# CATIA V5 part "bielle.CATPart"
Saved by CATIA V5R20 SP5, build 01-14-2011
Part number: bielle
Bounding box of the stored display mesh (mm): x 0 to 20, y -95 to 85, z -10 to 20
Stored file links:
  M:\EU_thinkMotion\IAO_2010\iao\IAO_MMS_Groupe2\IAO_MMS_Groupe2\rwatrin\rwatrin\bielle.CATPart
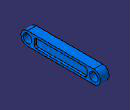
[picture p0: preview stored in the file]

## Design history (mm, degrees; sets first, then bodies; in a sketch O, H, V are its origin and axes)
Parameters
  `Longueur bielle` = 225.81 mm
Set1
  Plane1: type Offset, RefPlane yz-plane, Offset 10
Body1 (main body)
  Sketch1 on yz-plane, origin (0, 0, 0), H (0, 1, 0), V (0, 0, 1)
    line L1 (-80, 20) -> (70, 20)
    arc A1 centre (70, 5) radius 15 from (70, 20) to (70, -10) cw
    point P3 (70, 5)
    line L2 (70, -10) -> (-80, -10)
    arc A2 centre (-80, 5) radius 15 from (-80, -10) to (-80, 20) cw
    point P6 (-80, 5)
    circle A3 centre (70, 5) radius 10
    point P7 (70, 5)
    circle A4 centre (-80, 5) radius 10
    radius A3 = 10
    radius A4 = 10
    distance P6 P7 = 150
    distance L1 L2 = 30
    horizontal: L1 H
    tangency: A1 L1, L2 A1, A2 L1, A2 L2
    coincidence: P3 P7
  Pad1: profile Sketch1, direction (1, 0, 0), length 20
  Sketch2 on end face of Pad1, origin (20, 0, 0), H (0, 1, 0), V (0, 0, 1)
    line L1 (-60, 15) -> (50, 15)
    line L2 (55, 10) -> (55, 0)
    line L3 (50, -5) -> (-60, -5)
    line L4 (-65, 0) -> (-65, 10)
    reference projected line E1 (70, 20) -> (-80, 20) from edge [face of Pad1 from Sketch1.L1 | end face of Pad1]
    reference projected line E2 (-80, -10) -> (70, -10) from edge [face of Pad1 from Sketch1.L2 | end face of Pad1]
    reference projected circle E3 centre (70, 5) radius 10 from edge [end face of Pad1 | face of Pad1 from Sketch1.A3]
    reference projected circle E4 centre (-80, 5) radius 10 from edge [end face of Pad1 | face of Pad1 from Sketch1.A4]
    arc A1 centre (-60, 10) radius 5 from (-60, 15) to (-65, 10) ccw
    arc A2 centre (-60, 0) radius 5 from (-60, -5) to (-65, 0) cw
    arc A3 centre (50, 0) radius 5 from (55, 0) to (50, -5) cw
    arc A4 centre (50, 10) radius 5 from (50, 15) to (55, 10) cw
    distance L1 E1 = 5
    distance L3 E2 = 5
    distance L2 E3 = 5
    distance L4 E4 = 5
    radius A1 = 5
    radius A2 = 5
    radius A3 = 5
    radius A4 = 5
    horizontal: L1 H
    vertical: L2 V, L4 V
    tangency: A1 L1, A1 L4, A2 L3, A2 L4, A3 L2, A3 L3, A4 L1, A4 L2
  Pocket1: profile Sketch2, direction (-1, 0, 0), length 5
  Mirror1: of Pocket1, Sketch2, about Plane1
